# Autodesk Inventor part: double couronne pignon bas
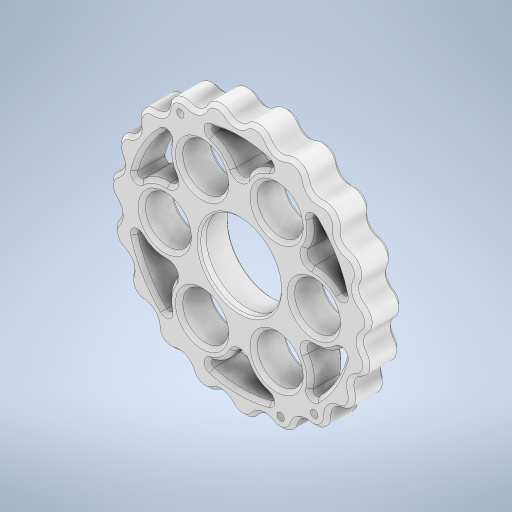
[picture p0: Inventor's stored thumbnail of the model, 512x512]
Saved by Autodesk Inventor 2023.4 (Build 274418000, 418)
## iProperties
Created: 2025-06
Part Number: double couronne pignon bas
Material: Steel
Document SubType Name: Modeling
Designer: mel
Density: 7.85 g/cm^3
Appearance: Par défaut
Author: mel
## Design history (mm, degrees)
feature "Discs Nul 0.00mm"
node "Solide1"
